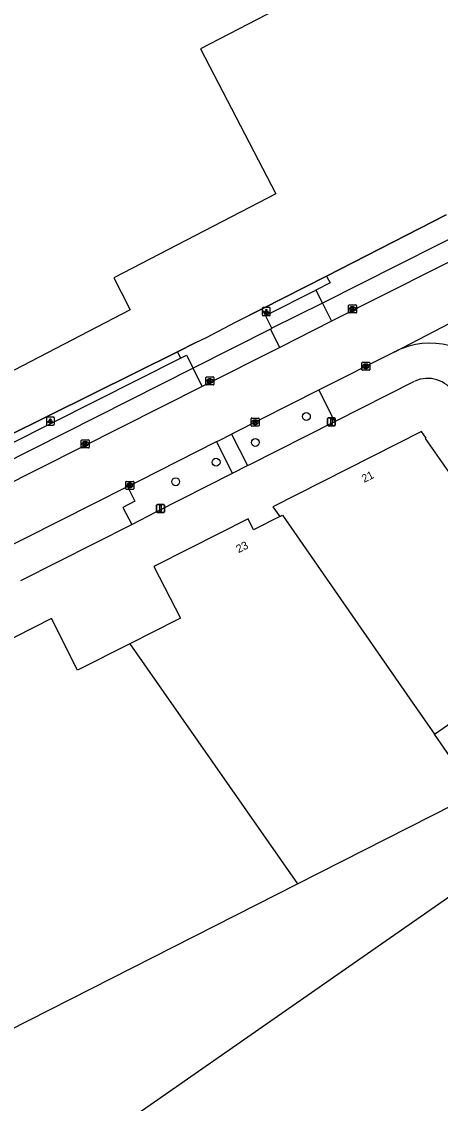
# Model space of a CAD drawing. Extents: x 156651 to 158072, y 387631 to 388990.
# Drawn here: x 157099.8 to 157152.2, y 388207.5 to 388342.7 of the extents above; entities that cross this region are included whole.
import ezdxf

# ---------------------------------------------------------------- set-up
doc = ezdxf.new("R2010")
doc.units = 0
for name, color, linetype in [('IMGEO_Berm_groen', 7, 'Continuous'), ('IMGEO_Boom', 7, 'Continuous'), ('IMGEO_Groenvoorziening', 7, 'Continuous'), ('IMGEO_Hek', 7, 'Continuous'), ('IMGEO_Kolk', 7, 'Continuous'), ('IMGEO_Lichtpunt', 7, 'Continuous'), ('IMGEO_Pand', 7, 'Continuous'), ('IMGEO_Pand_nummerreeks', 7, 'Continuous'), ('IMGEO_Rijbaan_lokaal_gesloten', 7, 'Continuous'), ('IMGEO_Rijbaan_lokaal_open', 7, 'Continuous'), ('IMGEO_Verkeersbordpaal', 7, 'Continuous'), ('IMGEO_Voetpad_open', 7, 'Continuous')]:
    doc.layers.add(name, color=color, linetype=linetype)

msp = doc.modelspace()

# ---------------------------------------------------------------- linework, layer by layer
at = {"layer": 'IMGEO_Berm_groen'}
for points in [[(157128.05, 388287.21), (157128.27, 388287.32), (157138.98, 388292.73)], [(157113.57, 388279.87), (157116.61, 388281.44), (157126.18, 388286.27)]]:
    msp.add_lwpolyline(points, dxfattribs=at)
at = {"layer": 'IMGEO_Boom'}
for centre in [(157135.41, 388293.36), (157129.03, 388290.11), (157124.12, 388287.64), (157119.07, 388285.2)]:
    msp.add_circle(centre, 0.489, dxfattribs=at)
at = {"layer": 'IMGEO_Groenvoorziening'}
for points in [[(157129.86, 388306.81), (157137.91, 388310.89)], [(157097.88, 388290.83), (157119.29, 388301.44)]]:
    msp.add_lwpolyline(points, dxfattribs=at)
at = {"layer": 'IMGEO_Hek'}
for points in [[(157152.9, 388318.56), (157137.91, 388310.89)], [(157137.91, 388310.89), (157129.86, 388306.81), (157128.28, 388306.02)], [(157121.59, 388302.59), (157119.29, 388301.44), (157097.88, 388290.83)]]:
    msp.add_lwpolyline(points, dxfattribs=at)
at = {"layer": 'IMGEO_Kolk'}
for p, q in [((157140.68, 388306.36), (157140.68, 388307.22)), ((157140.75, 388307.29), (157141.61, 388307.29)), ((157141.19, 388306.51), (157141.16, 388306.51)), ((157141.17, 388307.07), (157141.19, 388307.07)), ((157141.68, 388307.22), (157141.68, 388306.36)), ((157141.61, 388306.29), (157140.75, 388306.29)), ((157142.34, 388299.2), (157142.34, 388300.06)), ((157142.41, 388300.13), (157143.27, 388300.13)), ((157142.83, 388299.91), (157142.85, 388299.91)), ((157143.34, 388300.06), (157143.34, 388299.2)), ((157122.85, 388297.37), (157122.85, 388298.22)), ((157122.92, 388298.29), (157123.77, 388298.29)), ((157123.85, 388298.22), (157123.85, 388297.37)), ((157143.27, 388299.13), (157142.41, 388299.13)), ((157142.85, 388299.35), (157142.82, 388299.35)), ((157123.77, 388297.29), (157122.92, 388297.29)), ((157123.33, 388298.07), (157123.36, 388298.07)), ((157123.36, 388297.51), (157123.33, 388297.51)), ((157128.5, 388292.22), (157128.5, 388293.07)), ((157128.57, 388293.14), (157129.42, 388293.14)), ((157128.98, 388292.92), (157129.01, 388292.92)), ((157129.5, 388293.07), (157129.5, 388292.22)), ((157129.42, 388292.14), (157128.57, 388292.14)), ((157129.01, 388292.36), (157128.98, 388292.36)), ((157107.26, 388289.51), (157107.26, 388290.36)), ((157107.33, 388290.43), (157108.18, 388290.43)), ((157107.74, 388290.21), (157107.77, 388290.21)), ((157108.26, 388290.36), (157108.26, 388289.51)), ((157108.18, 388289.43), (157107.33, 388289.43)), ((157107.77, 388289.65), (157107.74, 388289.65)), ((157112.84, 388284.32), (157112.84, 388285.17)), ((157112.91, 388285.25), (157113.77, 388285.25)), ((157113.33, 388285.03), (157113.35, 388285.03)), ((157113.84, 388285.17), (157113.84, 388284.32)), ((157113.77, 388284.25), (157112.91, 388284.25)), ((157113.35, 388284.47), (157113.33, 388284.47))]:
    msp.add_line(p, q, dxfattribs=at)
for points in [[(157140.68, 388306.36), (157140.68, 388307.22)], [(157140.75, 388307.29), (157141.61, 388307.29)], [(157141, 388306.99), (157141.12, 388306.99), (157141.12, 388306.84), (157141.25, 388306.99), (157141.42, 388306.99), (157141.27, 388306.84), (157141.42, 388306.59), (157141.27, 388306.59), (157141.19, 388306.76), (157141.12, 388306.69), (157141.12, 388306.59), (157141, 388306.59), (157141, 388306.99)], [(157141.68, 388307.22), (157141.68, 388306.36)], [(157141.61, 388306.29), (157140.75, 388306.29)], [(157142.34, 388299.2), (157142.34, 388300.06)], [(157142.41, 388300.13), (157143.27, 388300.13)], [(157142.66, 388299.83), (157142.78, 388299.83), (157142.78, 388299.68), (157142.91, 388299.83), (157143.08, 388299.83), (157142.93, 388299.68), (157143.08, 388299.43), (157142.93, 388299.43), (157142.85, 388299.6), (157142.78, 388299.53), (157142.78, 388299.43), (157142.66, 388299.43), (157142.66, 388299.83)], [(157143.34, 388300.06), (157143.34, 388299.2)], [(157122.85, 388297.37), (157122.85, 388298.22)], [(157122.92, 388298.29), (157123.77, 388298.29)], [(157123.85, 388298.22), (157123.85, 388297.37)], [(157143.27, 388299.13), (157142.41, 388299.13)], [(157123.77, 388297.29), (157122.92, 388297.29)], [(157123.17, 388297.99), (157123.29, 388297.99), (157123.29, 388297.84), (157123.42, 388297.99), (157123.58, 388297.99), (157123.44, 388297.84), (157123.59, 388297.59), (157123.44, 388297.59), (157123.35, 388297.76), (157123.29, 388297.69), (157123.29, 388297.59), (157123.17, 388297.59), (157123.17, 388297.99)], [(157128.5, 388292.22), (157128.5, 388293.07)], [(157128.57, 388293.14), (157129.42, 388293.14)], [(157128.82, 388292.84), (157128.94, 388292.84), (157128.94, 388292.69), (157129.07, 388292.84), (157129.23, 388292.84), (157129.09, 388292.69), (157129.24, 388292.44), (157129.09, 388292.44), (157129, 388292.61), (157128.94, 388292.54), (157128.94, 388292.44), (157128.82, 388292.44), (157128.82, 388292.84)], [(157129.5, 388293.07), (157129.5, 388292.22)], [(157129.42, 388292.14), (157128.57, 388292.14)], [(157107.26, 388289.51), (157107.26, 388290.36)], [(157107.33, 388290.43), (157108.18, 388290.43)], [(157107.58, 388290.13), (157107.7, 388290.13), (157107.7, 388289.98), (157107.83, 388290.13), (157107.99, 388290.13), (157107.85, 388289.98), (157108, 388289.73), (157107.85, 388289.73), (157107.76, 388289.9), (157107.7, 388289.83), (157107.7, 388289.73), (157107.58, 388289.73), (157107.58, 388290.13)], [(157108.26, 388290.36), (157108.26, 388289.51)], [(157108.18, 388289.43), (157107.33, 388289.43)], [(157112.84, 388284.32), (157112.84, 388285.17)], [(157112.91, 388285.25), (157113.77, 388285.25)], [(157113.16, 388284.95), (157113.28, 388284.95), (157113.28, 388284.8), (157113.41, 388284.95), (157113.58, 388284.95), (157113.43, 388284.8), (157113.58, 388284.55), (157113.43, 388284.55), (157113.35, 388284.71), (157113.28, 388284.64), (157113.28, 388284.55), (157113.16, 388284.55), (157113.16, 388284.95)], [(157113.84, 388285.17), (157113.84, 388284.32)], [(157113.77, 388284.25), (157112.91, 388284.25)]]:
    msp.add_lwpolyline(points, dxfattribs=at)
for centre, start, end in [((157140.75, 388307.22), 91.552, 178.448), ((157140.75, 388307.22), 91.552, 178.448), ((157140.75, 388306.37), 181.552, 268.448), ((157140.75, 388306.37), 181.552, 268.448), ((157141.6, 388307.22), 1.552, 88.448), ((157141.6, 388307.22), 1.552, 88.448), ((157141.6, 388306.37), 271.552, 358.448), ((157141.6, 388306.37), 271.552, 358.448), ((157142.42, 388300.06), 91.552, 178.448), ((157142.42, 388300.06), 91.552, 178.448), ((157143.26, 388300.06), 1.552, 88.448), ((157143.26, 388300.06), 1.552, 88.448), ((157122.92, 388298.22), 91.552, 178.448), ((157122.92, 388298.22), 91.552, 178.448), ((157123.77, 388298.22), 1.552, 88.448), ((157123.77, 388298.22), 1.552, 88.448), ((157142.42, 388299.21), 181.552, 268.448), ((157142.42, 388299.21), 181.552, 268.448), ((157143.26, 388299.21), 271.552, 358.448), ((157143.26, 388299.21), 271.552, 358.448), ((157122.92, 388297.37), 181.552, 268.448), ((157122.92, 388297.37), 181.552, 268.448), ((157123.77, 388297.37), 271.552, 358.448), ((157123.77, 388297.37), 271.552, 358.448), ((157128.57, 388293.07), 91.552, 178.448), ((157128.57, 388293.07), 91.552, 178.448), ((157129.42, 388293.07), 1.552, 88.448), ((157129.42, 388293.07), 1.552, 88.448), ((157128.57, 388292.22), 181.552, 268.448), ((157128.57, 388292.22), 181.552, 268.448), ((157129.42, 388292.22), 271.552, 358.448), ((157129.42, 388292.22), 271.552, 358.448), ((157107.33, 388290.36), 91.552, 178.448), ((157107.33, 388290.36), 91.552, 178.448), ((157108.18, 388290.36), 1.552, 88.448), ((157108.18, 388290.36), 1.552, 88.448), ((157107.33, 388289.51), 181.552, 268.448), ((157107.33, 388289.51), 181.552, 268.448), ((157108.18, 388289.51), 271.552, 358.448), ((157108.18, 388289.51), 271.552, 358.448), ((157112.92, 388285.17), 91.552, 178.448), ((157112.92, 388285.17), 91.552, 178.448), ((157113.76, 388285.17), 1.552, 88.448), ((157113.76, 388285.17), 1.552, 88.448), ((157112.92, 388284.32), 181.552, 268.448), ((157112.92, 388284.32), 181.552, 268.448), ((157113.76, 388284.32), 271.552, 358.448), ((157113.76, 388284.32), 271.552, 358.448)]:
    msp.add_arc(centre, 0.0765, start, end, dxfattribs=at)
for centre, major_axis, ratio, start_param, end_param in [((157141.17, 388306.79), (-0.387, 0.002), 0.722429, 4.712389, 7.853982), ((157141.19, 388306.79), (-0.39, 0.002), 0.717154, 1.570796, 4.712389), ((157142.83, 388299.63), (-0.387, 0.002), 0.722429, 4.712389, 7.853982), ((157142.85, 388299.63), (-0.39, 0.002), 0.717154, 1.570796, 4.712389), ((157123.33, 388297.79), (-0.387, 0.002), 0.722429, 4.712389, 7.853982), ((157123.36, 388297.79), (-0.39, 0.002), 0.717154, 1.570796, 4.712389), ((157128.98, 388292.64), (-0.387, 0.002), 0.722429, 4.712389, 7.853982), ((157129.01, 388292.64), (-0.39, 0.002), 0.717154, 1.570796, 4.712389), ((157107.74, 388289.93), (-0.387, 0.002), 0.722429, 4.712389, 7.853982), ((157107.77, 388289.93), (-0.39, 0.002), 0.717154, 1.570796, 4.712389), ((157113.33, 388284.75), (-0.387, 0.002), 0.722429, 4.712389, 7.853982), ((157113.35, 388284.75), (-0.39, 0.002), 0.717154, 1.570796, 4.712389)]:
    msp.add_ellipse(centre, major_axis=major_axis, ratio=ratio, start_param=start_param, end_param=end_param, dxfattribs=at)
at = {"layer": 'IMGEO_Lichtpunt'}
for p, q in [((157129.9, 388306.85), (157129.9, 388306.04)), ((157129.9, 388306.85), (157129.9, 388306.04)), ((157130.8, 388306.95), (157130, 388306.95)), ((157130.8, 388306.95), (157130, 388306.95)), ((157130.9, 388306.04), (157130.9, 388306.85)), ((157130.9, 388306.04), (157130.9, 388306.85)), ((157130, 388305.95), (157130.8, 388305.95)), ((157130, 388305.95), (157130.8, 388305.95)), ((157102.9, 388293.19), (157102.9, 388292.38)), ((157102.9, 388293.19), (157102.9, 388292.38)), ((157103.8, 388293.28), (157102.99, 388293.28)), ((157103.8, 388293.28), (157102.99, 388293.28)), ((157103.9, 388292.38), (157103.9, 388293.19)), ((157103.9, 388292.38), (157103.9, 388293.19)), ((157102.99, 388292.28), (157103.8, 388292.28)), ((157102.99, 388292.28), (157103.8, 388292.28))]:
    msp.add_line(p, q, dxfattribs=at)
for points in [[(157130.28, 388306.51), (157130.32, 388306.49), (157130.13, 388306.22), (157130.09, 388306.25), (157130.28, 388306.51)], [(157130.38, 388306.47), (157130.43, 388306.47), (157130.43, 388306.14), (157130.38, 388306.14), (157130.38, 388306.47)], [(157130.49, 388306.49), (157130.53, 388306.51), (157130.71, 388306.25), (157130.68, 388306.22), (157130.49, 388306.49)], [(157103.27, 388292.85), (157103.31, 388292.82), (157103.12, 388292.56), (157103.09, 388292.59), (157103.27, 388292.85)], [(157103.37, 388292.8), (157103.42, 388292.8), (157103.42, 388292.48), (157103.37, 388292.48), (157103.37, 388292.8)], [(157103.48, 388292.82), (157103.52, 388292.85), (157103.71, 388292.59), (157103.67, 388292.56), (157103.48, 388292.82)]]:
    msp.add_lwpolyline(points, dxfattribs=at)
for centre in [(157130.4, 388306.65), (157103.4, 388292.98)]:
    msp.add_circle(centre, 0.0994, dxfattribs=at)
for centre, start, end in [((157130, 388306.85), 90, 180), ((157130, 388306.85), 90, 180), ((157130.8, 388306.85), 0, 90), ((157130.8, 388306.85), 0, 90), ((157130, 388306.04), 180, 270), ((157130, 388306.04), 180, 270), ((157130.8, 388306.04), 270, 0), ((157130.8, 388306.04), 270, 360), ((157102.99, 388293.19), 90, 180), ((157102.99, 388293.19), 90, 180), ((157103.8, 388293.19), 0, 90), ((157103.8, 388293.19), 0, 90), ((157102.99, 388292.38), 180, 270), ((157102.99, 388292.38), 180, 270), ((157103.8, 388292.38), 270, 0), ((157103.8, 388292.38), 270, 360)]:
    msp.add_arc(centre, 0.0946, start, end, dxfattribs=at)
at = {"layer": 'IMGEO_Pand'}
for points in [[(157139.9, 388348.49), (157122.17, 388339.28)], [(157122.17, 388339.28), (157131.58, 388321.18), (157130.53, 388320.64), (157127.17, 388318.9), (157111.34, 388310.69), (157112.25, 388308.9), (157113.39, 388306.68), (157098.86, 388299.14)], [(157151.41, 388253.67), (157168.09, 388265.19), (157150.3, 388290.6), (157150.38, 388290.66), (157149.79, 388291.49), (157131.21, 388282.05), (157132.08, 388280.85)], [(157132.08, 388280.85), (157128.81, 388279.2), (157128.12, 388280.55), (157120.81, 388276.87), (157116.32, 388274.61), (157119.65, 388268.14), (157119.25, 388267.93), (157113.32, 388264.95)], [(157132.08, 388280.85), (157132.43, 388281.03), (157148.35, 388258.1), (157151.41, 388253.67)], [(157113.32, 388264.95), (157106.8, 388261.68), (157103.55, 388268.11), (157089.99, 388261.26), (157089.63, 388261.95), (157088.74, 388261.5), (157088.9, 388260.7), (157085.93, 388259.25), (157085.37, 388259.79), (157084.48, 388259.33), (157084.8, 388258.65), (157072.86, 388252.59), (157074.17, 388250), (157076.09, 388246.18), (157074.56, 388245.32), (157077.42, 388241.22), (157095.54, 388215.31), (157134.3, 388234.97)], [(157113.32, 388264.95), (157134.3, 388234.97)], [(157134.3, 388234.97), (157156.54, 388246.26), (157151.41, 388253.67)], [(157182.85, 388224.57), (157183.01, 388224.68), (157182.4, 388225.55), (157191.37, 388231.8), (157187.21, 388237.77), (157186.5, 388237.28), (157185.37, 388238.89), (157186.08, 388239.41), (157180.54, 388247.36), (157171.55, 388241.12), (157169.23, 388244.45), (157165.12, 388241.59), (157106, 388200.43), (157119.75, 388180.62), (157178.91, 388221.83), (157182.85, 388224.57)]]:
    msp.add_lwpolyline(points, dxfattribs=at)
at = {"layer": 'IMGEO_Rijbaan_lokaal_gesloten'}
for points in [[(157158.27, 388315.18), (157138.55, 388305.25)], [(157146.43, 388301.43), (157146.45, 388301.45), (157171.24, 388314.32)], [(157138.55, 388305.25), (157132.07, 388301.98)], [(157132.07, 388301.98), (157122.4, 388297.11)], [(157136.98, 388296.67), (157146.43, 388301.43)], [(157122.4, 388297.11), (157066.55, 388268.97)], [(157126.05, 388291.16), (157126.27, 388291.27), (157136.98, 388296.67)], [(157113.04, 388284.61), (157114.58, 388285.37), (157124.19, 388290.22)], [(157124.19, 388290.22), (157124.49, 388290.37), (157126.05, 388291.16)], [(157096.1, 388276.06), (157113.04, 388284.61)]]:
    msp.add_lwpolyline(points, dxfattribs=at)
for centre, radius, start, end in [((157150.9, 388292.74), 9.77, 31.3129, 111.2197), ((157150.79, 388293.01), 9.47, 111.1634, 117.3635)]:
    msp.add_arc(centre, radius, start, end, dxfattribs=at)
at = {"layer": 'IMGEO_Rijbaan_lokaal_open'}
for points in [[(157113.04, 388284.61), (157113.97, 388282.76), (157112.47, 388281.98), (157113.57, 388279.87)], [(157099.73, 388272.88), (157113.57, 388279.87)]]:
    msp.add_lwpolyline(points, dxfattribs=at)
at = {"layer": 'IMGEO_Verkeersbordpaal'}
for p, q in [((157138.04, 388292.29), (157138.04, 388293.09)), ((157138.04, 388293.09), (157138.04, 388292.29)), ((157138.14, 388293.19), (157138.92, 388293.19)), ((157138.92, 388293.19), (157138.14, 388293.19)), ((157139.02, 388293.09), (157139.02, 388292.29)), ((157139.02, 388292.29), (157139.02, 388293.09)), ((157138.92, 388292.19), (157138.14, 388292.19)), ((157138.14, 388292.19), (157138.92, 388292.19)), ((157116.68, 388281.46), (157116.68, 388282.26)), ((157116.68, 388282.26), (157116.68, 388281.46)), ((157116.78, 388282.36), (157117.57, 388282.36)), ((157117.57, 388282.36), (157116.78, 388282.36)), ((157117.67, 388282.26), (157117.67, 388281.46)), ((157117.67, 388281.46), (157117.67, 388282.26)), ((157117.57, 388281.36), (157116.78, 388281.36)), ((157116.78, 388281.36), (157117.57, 388281.36))]:
    msp.add_line(p, q, dxfattribs=at)
for points in [[(157138.46, 388293.07), (157138.61, 388293.07), (157138.61, 388292.32), (157138.46, 388292.32), (157138.46, 388293.07)], [(157117.1, 388282.23), (157117.25, 388282.23), (157117.25, 388281.48), (157117.1, 388281.48), (157117.1, 388282.23)]]:
    msp.add_lwpolyline(points, dxfattribs=at)
for centre, start, end in [((157138.14, 388293.09), 90, 180), ((157138.14, 388293.09), 90, 180), ((157138.92, 388293.09), 0, 90), ((157138.92, 388293.09), 360, 90), ((157138.14, 388292.29), 180, 270), ((157138.14, 388292.29), 180, 270), ((157138.92, 388292.29), 270, 0), ((157138.92, 388292.29), 270, 0), ((157116.78, 388282.26), 90, 180), ((157116.78, 388282.26), 90, 180), ((157117.57, 388282.26), 0, 90), ((157117.57, 388282.26), 360, 90), ((157116.78, 388281.46), 180, 270), ((157116.78, 388281.46), 180, 270), ((157117.57, 388281.46), 270, 0), ((157117.57, 388281.46), 270, 0)]:
    msp.add_arc(centre, 0.1, start, end, dxfattribs=at)
at = {"layer": 'IMGEO_Voetpad_open'}
for points in [[(157137.91, 388310.89), (157152.9, 388318.56)], [(157156.6, 388317.18), (157137.41, 388307.52)], [(157137.91, 388310.89), (157138.36, 388310.04), (157136.58, 388309.14)], [(157130.28, 388305.98), (157136.58, 388309.14)], [(157136.58, 388309.14), (157137.41, 388307.52)], [(157119.29, 388301.44), (157121.59, 388302.59), (157122.91, 388303.24), (157126.54, 388305.13), (157128.28, 388306.02), (157129.86, 388306.81)], [(157130.28, 388305.98), (157129.86, 388306.81)], [(157137.41, 388307.52), (157131.09, 388304.37)], [(157137.41, 388307.52), (157138.55, 388305.25)], [(157131.09, 388304.37), (157130.28, 388305.98)], [(157130.92, 388304.28), (157121.25, 388299.39)], [(157130.92, 388304.28), (157131.09, 388304.37)], [(157132.07, 388301.98), (157130.92, 388304.28)], [(157119.29, 388301.44), (157119.69, 388300.64)], [(157119.69, 388300.64), (157120.42, 388301), (157121.25, 388299.39)], [(157097.88, 388290.83), (157098.35, 388289.88), (157119.69, 388300.64)], [(157121.25, 388299.39), (157065.04, 388271.04), (157057.93, 388267.33)], [(157122.4, 388297.11), (157121.25, 388299.39)], [(157138.98, 388292.73), (157148.94, 388297.75)], [(157138.98, 388292.73), (157136.98, 388296.67)], [(157126.18, 388286.27), (157124.19, 388290.22)], [(157126.05, 388291.16), (157128.05, 388287.21)], [(157126.18, 388286.27), (157128.05, 388287.21)]]:
    msp.add_lwpolyline(points, dxfattribs=at)
msp.add_arc((157150.57, 388294.22), 3.89, 30.7668, 114.6814, dxfattribs=at)

# ---------------------------------------------------------------- texts
at = {"layer": 'IMGEO_Pand_nummerreeks'}
for s, rotation, p in [('21', 26.9577, (157142.63, 388285.05)), ('23', 26.7113, (157126.92, 388276.27))]:
    msp.add_text(s, height=1, rotation=rotation, dxfattribs=at).set_placement(p)

doc.saveas('drawing.dxf')
